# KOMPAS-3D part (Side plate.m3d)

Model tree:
1. X Axis
2. Y Axis
3. Z Axis
4. Origin  (labels: D:\Program Files\ASCON\KOMPAS-3D V10\Sys\GRAPHIC_EN.LYT; Plate 02)
     Wall Thickness 1 = 1; Wall Thickness 2 = 1; Distance 1 = 10; Distance 2 = 10

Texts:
  Plate 02
  Three Point Plane
  Plane at Angle
  Line and Point Plane
  Axis through Two Vertices
  Axis of Feature
  Axis of Conical Surface
  Axis through Edge
  Trim by Surface
  Trim by Sketch
  Feature with No History
  Intersection Axis of Two Planes
  Two Line Plane
  Line and Face Plane
  Bend by line
  Hole in sheet body
  Cut in sheet body
  Point in CM
  Linear Dimension from Line to Point
  Surface Finish Symbol
  Geometric Tolerance Symbol
  Leader #1
  Leader #2
  Leader #3
  Shape Deviations and Datum
  Node point number
  Mark of coordination axis
  Node point designation
  Mark/Reference designation with leader
  Mark/reference designation on line
  Mark/Reference designation without leader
